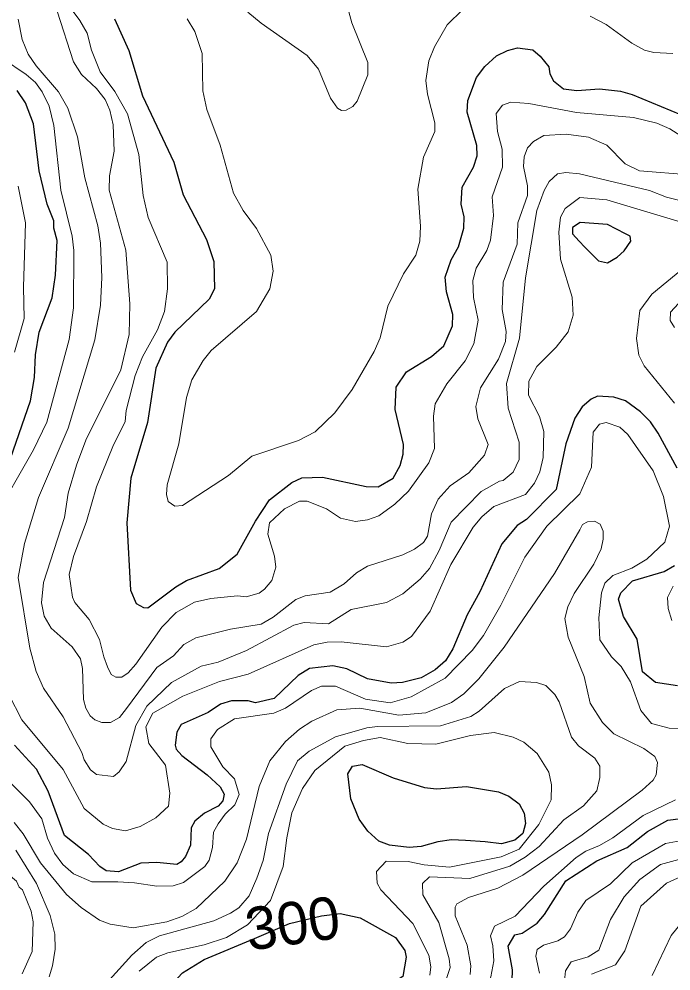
# Model space of a CAD drawing. Extents: x 673.6 to 698.9, y 7012 to 7040.1.
# Drawn here: x 682.325 to 683.554, y 7019.584 to 7021.378 of the extents above; entities that cross this region are included whole.
import ezdxf
from ezdxf.enums import TextEntityAlignment as Align

# ---------------------------------------------------------------- set-up
doc = ezdxf.new("R2010")
doc.units = 0
doc.header["$LTSCALE"] = 0.032
doc.layers.add('1', color=7, linetype='Continuous', lineweight=25)
doc.layers.add('2', color=7, linetype='Continuous', lineweight=13)
doc.layers.add('61', color=7, linetype='Continuous')

msp = doc.modelspace()

# ---------------------------------------------------------------- linework, layer by layer
at = {"layer": '1'}
for points in [[(682.5051, 7021.3782), (682.5322, 7021.3183), (682.5575, 7021.2333), (682.6166, 7021.1083), (682.6346, 7021.0462), (682.6782, 7020.9624), (682.6922, 7020.9209), (682.6932, 7020.8691), (682.6835, 7020.8501), (682.6189, 7020.7875), (682.6051, 7020.7686), (682.5829, 7020.72), (682.5674, 7020.6173), (682.536, 7020.5124), (682.528, 7020.4286), (682.5349, 7020.3014), (682.546, 7020.2763), (682.5597, 7020.2687)], [(682.7363, 7020.3695), (682.7705, 7020.4316), (682.7972, 7020.4719), (682.8393, 7020.5047), (682.8583, 7020.5134), (682.8969, 7020.5142), (682.9792, 7020.4972), (683.0017, 7020.4962), (683.0302, 7020.5129), (683.0432, 7020.5367), (683.0489, 7020.5578), (683.0497, 7020.5758), (683.0341, 7020.6419), (683.0358, 7020.6839), (683.0555, 7020.713), (683.1026, 7020.7421), (683.1256, 7020.7619), (683.1417, 7020.7997), (683.1424, 7020.8211), (683.1307, 7020.8634), (683.1279, 7020.8913), (683.1392, 7020.9238), (683.1534, 7020.9482), (683.1634, 7020.9839), (683.1639, 7021.0051), (683.1583, 7021.029), (683.1599, 7021.0611), (683.1814, 7021.0988), (683.1886, 7021.1202), (683.1879, 7021.1393), (683.1698, 7021.2021), (683.1708, 7021.2242), (683.1869, 7021.2673), (683.2029, 7021.2885), (683.2251, 7021.3082), (683.2454, 7021.3186), (683.2647, 7021.3235), (683.2935, 7021.3196), (683.3072, 7021.3077), (683.3232, 7021.2874), (683.3251, 7021.2743), (683.3325, 7021.2612), (683.3514, 7021.2465), (683.3764, 7021.2431), (683.4188, 7021.2462), (683.4586, 7021.2415), (683.4807, 7021.2355), (683.6263, 7021.175)], [(682.3087, 7020.5499), (682.3464, 7020.6584), (682.3545, 7020.7024), (682.3561, 7020.7447), (682.3627, 7020.7874), (682.3875, 7020.8523), (682.394, 7020.895), (682.3972, 7020.9604), (682.3908, 7020.9838), (682.3906, 7020.9973), (682.3781, 7021.0286), (682.3628, 7021.0915), (682.3521, 7021.1801), (682.3375, 7021.2197), (682.3216, 7021.243)], [(683.5653, 7020.5312), (683.5294, 7020.5975), (683.5148, 7020.6185), (683.4964, 7020.6377), (683.4679, 7020.6585), (683.4458, 7020.6653), (683.415, 7020.667), (683.4032, 7020.6612), (683.3863, 7020.6468), (683.3725, 7020.6255), (683.3553, 7020.5771), (683.3371, 7020.4911), (683.2812, 7020.4349), (683.2635, 7020.4237), (683.2348, 7020.3891), (683.1937, 7020.2984), (683.1696, 7020.255), (683.1426, 7020.1912), (683.1286, 7020.1683)], [(682.5597, 7020.2687), (682.568, 7020.268), (682.6205, 7020.3077), (682.6409, 7020.3196), (682.7025, 7020.3423), (682.7363, 7020.3695)], [(683.5658, 7020.1213), (683.5248, 7020.1276), (683.5002, 7020.1477), (683.4902, 7020.2093), (683.4642, 7020.2517), (683.455, 7020.2845), (683.459, 7020.2964), (683.4812, 7020.3194), (683.5411, 7020.3369), (683.56, 7020.3482)], [(683.1286, 7020.1683), (683.1092, 7020.1512), (683.0831, 7020.1361), (683.0477, 7020.1279), (683.0263, 7020.1264), (682.982, 7020.1347)], [(682.982, 7020.1347), (682.9425, 7020.1535), (682.9166, 7020.1591), (682.8727, 7020.1543), (682.851, 7020.141), (682.8058, 7020.0973), (682.7707, 7020.0894), (682.7569, 7020.0928), (682.7257, 7020.0933), (682.7047, 7020.0868), (682.6816, 7020.0713), (682.6309, 7020.0484), (682.6224, 7020.0338), (682.6192, 7020.0093), (682.621, 7020.002), (682.6316, 7019.99), (682.6799, 7019.9537), (682.7043, 7019.9309), (682.7116, 7019.9175), (682.7094, 7019.9045), (682.7006, 7019.8948), (682.6747, 7019.8812), (682.6562, 7019.8666), (682.6496, 7019.854), (682.648, 7019.8214), (682.6386, 7019.7998), (682.6306, 7019.7895), (682.6227, 7019.785), (682.5846, 7019.7885), (682.5545, 7019.7869), (682.5126, 7019.7706), (682.4892, 7019.7728), (682.4772, 7019.7809), (682.4561, 7019.8036), (682.4107, 7019.8393), (682.3797, 7019.9226), (682.3578, 7019.9644), (682.3168, 7020.0095)], [(683.2543, 7019.5654), (683.2551, 7019.5863), (683.2471, 7019.6308), (683.2597, 7019.6522), (683.2732, 7019.6555), (683.3018, 7019.6742), (683.3156, 7019.6907), (683.3555, 7019.754), (683.4137, 7019.7918), (683.4713, 7019.8169), (683.5096, 7019.8466), (683.5478, 7019.8682), (683.5917, 7019.874)]]:
    msp.add_lwpolyline(points, dxfattribs=at)
for points in [[(683.4678, 7020.973), (683.4341, 7020.9906), (683.3828, 7020.9944), (683.3682, 7020.9852), (683.3682, 7020.973), (683.3805, 7020.9592), (683.3912, 7020.9477), (683.4173, 7020.9224), (683.4341, 7020.9186), (683.4525, 7020.9293), (683.4655, 7020.9408), (683.4778, 7020.9592), (683.477, 7020.9684)], [(683.2038, 7019.8274), (683.1666, 7019.8296), (683.1402, 7019.8312), (683.1145, 7019.8274), (683.0826, 7019.8184), (683.0603, 7019.8166), (683.0234, 7019.8211), (683.0033, 7019.8287), (682.9821, 7019.8473), (682.9661, 7019.8698), (682.9504, 7019.9082), (682.9446, 7019.9558), (682.9538, 7019.97), (682.9715, 7019.9732), (683.0304, 7019.9478), (683.0889, 7019.93), (683.1116, 7019.9275), (683.1681, 7019.9315), (683.2286, 7019.9217), (683.2483, 7019.9136), (683.2677, 7019.8991), (683.2771, 7019.8813), (683.2797, 7019.8618), (683.2745, 7019.843), (683.2595, 7019.8303), (683.2344, 7019.8238)], [(682.7689, 7019.645), (682.8348, 7019.6735), (682.8948, 7019.6881), (682.9305, 7019.6926), (682.9679, 7019.6841), (683.0345, 7019.6474), (683.0518, 7019.6229), (683.0546, 7019.6099), (683.0482, 7019.5736), (683.0237, 7019.5578), (682.9759, 7019.5445), (682.9475, 7019.5267), (682.8657, 7019.4469), (682.8237, 7019.4132), (682.7678, 7019.4058), (682.6934, 7019.4212), (682.6532, 7019.4424), (682.6206, 7019.4716), (682.6079, 7019.4891), (682.5978, 7019.5153), (682.6028, 7019.5443), (682.6071, 7019.5529), (682.6329, 7019.5804), (682.6738, 7019.6055)]]:
    msp.add_lwpolyline(points, close=True, dxfattribs=at)
at = {"layer": '2'}
for points in [[(682.9372, 7021.4266), (682.9523, 7021.3707), (682.9822, 7021.296), (682.9825, 7021.2727), (682.9622, 7021.2227), (682.9541, 7021.2127), (682.9417, 7021.206), (682.933, 7021.2053), (682.9252, 7021.21), (682.9118, 7021.2283), (682.8892, 7021.2832), (682.8681, 7021.3088), (682.7811, 7021.3699), (682.7563, 7021.3909)], [(683.033, 7020.4637), (683.0034, 7020.4417), (682.9815, 7020.4338), (682.959, 7020.4312), (682.9307, 7020.437), (682.9045, 7020.4547), (682.8682, 7020.469), (682.8539, 7020.4691), (682.8251, 7020.4551), (682.7973, 7020.4285), (682.7942, 7020.4073), (682.8065, 7020.3654), (682.8089, 7020.3451), (682.8012, 7020.3197), (682.7879, 7020.3033), (682.7778, 7020.2961), (682.7531, 7020.2892), (682.7367, 7020.2907), (682.6862, 7020.2857), (682.6557, 7020.2792), (682.6214, 7020.2592), (682.5939, 7020.2317), (682.5454, 7020.1619), (682.5307, 7020.1461), (682.5187, 7020.1379), (682.5076, 7020.1379), (682.4988, 7020.1425), (682.4919, 7020.1573), (682.4846, 7020.1757), (682.4764, 7020.2086), (682.4571, 7020.2463), (682.4304, 7020.2781), (682.4257, 7020.2886), (682.4195, 7020.3309), (682.428, 7020.365), (682.4519, 7020.4307), (682.471, 7020.4962), (682.5016, 7020.5723), (682.5253, 7020.6192), (682.5272, 7020.6403), (682.5438, 7020.7063), (682.558, 7020.7412), (682.5861, 7020.7924), (682.5992, 7020.8265), (682.6051, 7020.8693), (682.6043, 7020.9198), (682.5681, 7021.0035), (682.5592, 7021.0455), (682.5508, 7021.1222), (682.5294, 7021.199), (682.5059, 7021.2411), (682.4782, 7021.2783), (682.4617, 7021.3191), (682.4532, 7021.3512), (682.4396, 7021.3752), (682.4137, 7021.4098)], [(682.3967, 7021.3927), (682.4278, 7021.297), (682.443, 7021.2731), (682.471, 7021.2466), (682.4872, 7021.226), (682.4962, 7021.2063), (682.5025, 7021.1782), (682.5041, 7021.1289), (682.4958, 7021.0825), (682.4951, 7021.0554), (682.5262, 7020.9423), (682.5337, 7020.8411), (682.5328, 7020.7833), (682.5171, 7020.7168), (682.4507, 7020.5841), (682.4332, 7020.5373), (682.4179, 7020.4841), (682.4106, 7020.4384), (682.3709, 7020.3158), (682.3677, 7020.2779), (682.3725, 7020.2527), (682.3857, 7020.2299), (682.4255, 7020.195), (682.4408, 7020.1723), (682.4449, 7020.1538), (682.4466, 7020.0956), (682.4508, 7020.0791)], [(683.1613, 7021.3957), (683.1316, 7021.3665), (683.108, 7021.3253), (683.0971, 7021.2989), (683.0917, 7021.2621), (683.0951, 7021.2359), (683.1089, 7021.1822), (683.1089, 7021.1659), (683.0876, 7021.1177), (683.0768, 7021.057), (683.0817, 7020.9874), (683.0802, 7020.9591), (683.0727, 7020.9325), (683.0496, 7020.8976), (683.0198, 7020.8365), (683.0055, 7020.777), (682.9943, 7020.7511), (682.9529, 7020.6796), (682.9205, 7020.6355), (682.8832, 7020.5999), (682.8519, 7020.5838), (682.7638, 7020.5543), (682.7196, 7020.5178), (682.6331, 7020.4609), (682.6184, 7020.4596), (682.6058, 7020.4688), (682.6028, 7020.4818), (682.6043, 7020.4999), (682.6265, 7020.5775), (682.6405, 7020.6645), (682.6507, 7020.698), (682.6722, 7020.7346), (682.687, 7020.753), (682.7728, 7020.8268), (682.7979, 7020.8694), (682.804, 7020.9028), (682.7998, 7020.933), (682.7724, 7020.9828), (682.7473, 7021.0168), (682.729, 7021.0499), (682.7044, 7021.1403), (682.6787, 7021.2071), (682.6717, 7021.2427), (682.6699, 7021.3128), (682.6564, 7021.3542), (682.6421, 7021.3778)], [(683.578, 7021.0341), (683.5452, 7021.0423), (683.5129, 7021.0549), (683.3814, 7021.0862), (683.3555, 7021.0886), (683.3398, 7021.0862), (683.3242, 7021.0718), (683.3145, 7021.0544), (683.3006, 7021.0168), (683.2795, 7020.8902), (683.2683, 7020.7764), (683.2437, 7020.6908), (683.2469, 7020.6443), (683.2677, 7020.5805), (683.2675, 7020.5479), (683.2565, 7020.5237), (683.2377, 7020.508), (683.2308, 7020.5072), (683.1958, 7020.4876), (683.1396, 7020.4297), (683.117, 7020.3766), (683.0984, 7020.3427), (683.0811, 7020.3222), (683.0481, 7020.2947), (683.0176, 7020.2786), (682.9508, 7020.265), (682.9081, 7020.238), (682.8625, 7020.2404), (682.8431, 7020.2357), (682.7539, 7020.1879), (682.7004, 7020.166), (682.6681, 7020.1582), (682.6124, 7020.1277), (682.5662, 7020.0833), (682.5453, 7020.0466), (682.5269, 7019.9789), (682.5139, 7019.9595), (682.5032, 7019.9506), (682.4712, 7019.9544), (682.4599, 7019.9628), (682.4476, 7019.9819), (682.4431, 7019.9959), (682.4081, 7020.0627), (682.3711, 7020.1169), (682.3572, 7020.1482), (682.3456, 7020.1925), (682.3234, 7020.3256), (682.3356, 7020.3898), (682.3617, 7020.4765), (682.4177, 7020.6067), (682.4679, 7020.773), (682.4786, 7020.8384), (682.4811, 7020.8906), (682.4788, 7020.9552), (682.4736, 7020.9883), (682.4491, 7021.0784), (682.435, 7021.1559), (682.4173, 7021.2095), (682.3994, 7021.2408), (682.3576, 7021.2894), (682.3425, 7021.3118), (682.3308, 7021.339), (682.3234, 7021.3775)], [(683.5573, 7021.3129), (683.5211, 7021.3146), (683.504, 7021.3191), (683.4796, 7021.332), (683.4315, 7021.3673), (683.4013, 7021.3832)], [(682.294, 7021.3036), (682.3388, 7021.2733), (682.3559, 7021.2581), (682.3689, 7021.2405), (682.3816, 7021.2135), (682.3907, 7021.1773), (682.4039, 7021.0554), (682.4252, 7020.9686), (682.4285, 7020.9413), (682.4276, 7020.8338), (682.4193, 7020.7739), (682.3774, 7020.6182), (682.3523, 7020.5662), (682.2756, 7020.4328)], [(683.584, 7021.1498), (683.5514, 7021.1706), (683.5271, 7021.1812), (683.4833, 7021.1922), (683.3755, 7021.2019), (683.2856, 7021.2183), (683.2521, 7021.2209), (683.236, 7021.2157), (683.224, 7021.1999), (683.2265, 7021.1655), (683.2355, 7021.1322), (683.2363, 7021.0988), (683.2166, 7021.0429), (683.219, 7021.0077), (683.2138, 7020.9608), (683.2064, 7020.9417), (683.1863, 7020.9081), (683.1805, 7020.8852), (683.1813, 7020.8532), (683.1902, 7020.8105), (683.1823, 7020.766), (683.1656, 7020.7336), (683.1311, 7020.6904), (683.109, 7020.6528)], [(682.5143, 7020.0619), (682.5277, 7020.0784), (682.5847, 7020.1558), (682.6163, 7020.1777), (682.6359, 7020.1989), (682.6583, 7020.2115), (682.7238, 7020.2284), (682.7811, 7020.2376), (682.8039, 7020.2505), (682.8468, 7020.284), (682.8641, 7020.2906), (682.9117, 7020.2981), (682.9377, 7020.3133), (682.961, 7020.3342), (682.982, 7020.3471), (683.0481, 7020.3681), (683.0701, 7020.3789), (683.0873, 7020.3917), (683.095, 7020.4031), (683.1021, 7020.4452), (683.1149, 7020.4729), (683.1374, 7020.4983), (683.173, 7020.5225), (683.2024, 7020.5558), (683.209, 7020.5758), (683.1898, 7020.6242), (683.1862, 7020.6476), (683.1946, 7020.6826), (683.2284, 7020.7367), (683.2417, 7020.7702), (683.2428, 7020.7891), (683.2355, 7020.8302), (683.2372, 7020.882), (683.2641, 7020.9535), (683.2651, 7020.9937), (683.2832, 7021.0449), (683.2832, 7021.0632), (683.2758, 7021.0998), (683.2768, 7021.1183), (683.2832, 7021.1353), (683.2949, 7021.1468), (683.3139, 7021.1584), (683.3562, 7021.161), (683.3982, 7021.1551), (683.4327, 7021.1398), (683.4674, 7021.1049), (683.4942, 7021.0916), (683.5891, 7021.0843)], [(682.3237, 7021.0627), (682.3371, 7020.9935), (682.3332, 7020.8727), (682.3348, 7020.8134), (682.3168, 7020.75)], [(682.3057, 7020.1047), (682.3304, 7020.0571), (682.4083, 7019.9638), (682.4478, 7019.8899), (682.4834, 7019.8605), (682.5011, 7019.8526), (682.5259, 7019.8479), (682.5531, 7019.8566), (682.583, 7019.8724), (682.6068, 7019.8949), (682.6092, 7019.9191), (682.601, 7019.9719), (682.5698, 7020.0126), (682.5641, 7020.0439), (682.5769, 7020.0697), (682.6335, 7020.1017), (682.7026, 7020.1294), (682.7571, 7020.1433), (682.8804, 7020.1986), (682.9058, 7020.2036), (682.9322, 7020.2044), (683.0174, 7020.1949), (683.0486, 7020.2039), (683.0645, 7020.2143), (683.1001, 7020.2623), (683.1389, 7020.3497), (683.181, 7020.4202), (683.1971, 7020.4396), (683.2199, 7020.4591), (683.2796, 7020.4821), (683.2963, 7020.5032), (683.3066, 7020.5243), (683.3128, 7020.5515), (683.3143, 7020.6004), (683.306, 7020.6287), (683.2849, 7020.6692), (683.2855, 7020.6955), (683.3011, 7020.7231), (683.337, 7020.7596), (683.36, 7020.7883), (683.3694, 7020.82), (683.3677, 7020.8539), (683.3454, 7020.9254), (683.3424, 7020.9759), (683.3455, 7021.0042), (683.3544, 7021.0208), (683.3821, 7021.0417), (683.4327, 7021.0368), (683.5836, 7020.9917)], [(683.5918, 7020.92), (683.5179, 7020.8591), (683.4952, 7020.8287), (683.4885, 7020.7755), (683.4933, 7020.7441), (683.5032, 7020.7244), (683.5604, 7020.6542)], [(683.5605, 7020.7963), (683.5519, 7020.8098), (683.5529, 7020.8251), (683.6056, 7020.8823)], [(683.109, 7020.6528), (683.1064, 7020.6292), (683.1081, 7020.5684), (683.0976, 7020.5417), (683.0591, 7020.4881), (683.033, 7020.4637)], [(682.2915, 7019.956), (682.3445, 7019.903), (682.3681, 7019.8708), (682.3788, 7019.834), (682.3917, 7019.8059), (682.4076, 7019.7848), (682.4279, 7019.767), (682.4624, 7019.7518), (682.5113, 7019.7522), (682.5426, 7019.7499), (682.585, 7019.744), (682.6155, 7019.7442), (682.6353, 7019.7506), (682.6753, 7019.7807), (682.6831, 7019.7928), (682.6898, 7019.8165), (682.6915, 7019.8453), (682.7004, 7019.8616), (682.7137, 7019.8797), (682.7319, 7019.8973), (682.7399, 7019.9167), (682.7308, 7019.9464), (682.7092, 7019.9688), (682.6866, 7020.0067), (682.6867, 7020.0216), (682.6988, 7020.039), (682.7314, 7020.0589), (682.8053, 7020.0697), (682.8273, 7020.0793), (682.8763, 7020.1123), (682.8951, 7020.1207), (682.9215, 7020.1205), (682.978, 7020.0963), (683.0246, 7020.0894), (683.0642, 7020.1007), (683.1284, 7020.1358), (683.1793, 7020.1877), (683.2002, 7020.2164), (683.2329, 7020.2735), (683.2781, 7020.3635), (683.3196, 7020.4224), (683.3821, 7020.4828), (683.4039, 7020.5331), (683.4071, 7020.599), (683.4188, 7020.6144), (683.4316, 7020.6176), (683.4573, 7020.6086), (683.4724, 7020.5952), (683.5198, 7020.5265), (683.5398, 7020.4782), (683.551, 7020.4222), (683.5418, 7020.3923), (683.5083, 7020.3597), (683.4798, 7020.343), (683.4441, 7020.3294), (683.4288, 7020.3147), (683.4229, 7020.2964), (683.418, 7020.2494), (683.4196, 7020.208), (683.4414, 7020.176), (683.4597, 7020.1575), (683.4777, 7020.1286), (683.4967, 7020.0749), (683.5169, 7020.0506), (683.5503, 7020.0417), (683.5783, 7020.041)], [(682.3159, 7019.8641), (682.3327, 7019.8422), (682.3658, 7019.788), (682.4143, 7019.728), (682.4422, 7019.7039), (682.4764, 7019.68), (682.497, 7019.6724), (682.5402, 7019.6654), (682.6037, 7019.6767), (682.632, 7019.6865), (682.6586, 7019.7015), (682.7129, 7019.7533), (682.7362, 7019.7876), (682.7538, 7019.8326), (682.7779, 7019.9315), (682.7978, 7019.9799), (682.8273, 7020.0164), (682.8536, 7020.0396), (682.8766, 7020.055), (682.924, 7020.076), (682.9676, 7020.0794), (683.041, 7020.0662), (683.0919, 7020.0703), (683.1398, 7020.09), (683.1633, 7020.1061), (683.1915, 7020.1348), (683.2391, 7020.1939), (683.3344, 7020.3327), (683.3819, 7020.415), (683.387, 7020.4253), (683.3966, 7020.4302), (683.4093, 7020.4313), (683.4205, 7020.4261), (683.4261, 7020.4128), (683.4257, 7020.3978), (683.4222, 7020.3797), (683.4082, 7020.3506), (683.3712, 7020.2951), (683.3593, 7020.27)], [(683.5578, 7020.3093), (683.547, 7020.2879), (683.5485, 7020.2668), (683.5556, 7020.2445)], [(683.3593, 7020.27), (683.3538, 7020.2479), (683.3601, 7020.2133), (683.3898, 7020.1389), (683.4012, 7020.0885)], [(683.1234, 7019.548), (683.1375, 7019.5906), (683.1354, 7019.6072), (683.116, 7019.6757), (683.0858, 7019.7273), (683.0853, 7019.7492), (683.0986, 7019.7614), (683.1743, 7019.7581), (683.2498, 7019.7817), (683.2791, 7019.7983), (683.305, 7019.8187), (683.3516, 7019.8686), (683.3887, 7019.895), (683.4142, 7019.9237), (683.4196, 7019.9487), (683.4194, 7019.9701), (683.4104, 7019.9849), (683.3795, 7020.0085), (683.3665, 7020.0246), (683.3431, 7020.0911), (683.3349, 7020.1049), (683.3179, 7020.122), (683.3002, 7020.1278), (683.2681, 7020.1294), (683.2398, 7020.116), (683.1925, 7020.0733), (683.1768, 7020.0637), (683.1191, 7020.0458), (683.0005, 7020.0449), (682.9808, 7020.0424), (682.9216, 7020.0252), (682.8718, 7019.998), (682.8501, 7019.98), (682.8285, 7019.9362), (682.7951, 7019.8428), (682.7852, 7019.7925), (682.7735, 7019.7589), (682.7585, 7019.7254), (682.7392, 7019.703), (682.7237, 7019.6929), (682.6923, 7019.6788), (682.5895, 7019.6505), (682.5644, 7019.6375), (682.5375, 7019.6141), (682.4834, 7019.554)], [(682.4508, 7020.0791), (682.4592, 7020.0649), (682.4677, 7020.0574), (682.4808, 7020.0523), (682.4974, 7020.0524), (682.5143, 7020.0619)], [(683.4012, 7020.0885), (683.4248, 7020.0522), (683.446, 7020.0307), (683.5028, 7020.0032), (683.523, 7019.9879), (683.528, 7019.9771), (683.526, 7019.9539), (683.5201, 7019.9435), (683.4995, 7019.925), (683.3861, 7019.8403), (683.2743, 7019.7645), (683.2276, 7019.7402), (683.1719, 7019.7224), (683.1502, 7019.7106), (683.1468, 7019.7043), (683.1469, 7019.6878), (683.1695, 7019.6326), (683.1764, 7019.594), (683.1754, 7019.5777)], [(682.5512, 7019.5834), (682.5839, 7019.6102), (682.6057, 7019.6183), (682.6742, 7019.6334), (682.7158, 7019.6471), (682.7559, 7019.6708), (682.7987, 7019.7166), (682.823, 7019.7807), (682.8296, 7019.835), (682.8393, 7019.8822), (682.859, 7019.9279), (682.8827, 7019.9617), (682.939, 7020.0075), (682.9742, 7020.0186), (683.0059, 7020.0237), (683.0576, 7020.0129), (683.1105, 7020.0113), (683.176, 7020.0276), (683.2207, 7020.0334), (683.2562, 7020.0247), (683.2765, 7020.0153), (683.3012, 7019.9939), (683.3233, 7019.9589), (683.3283, 7019.9348), (683.328, 7019.9063), (683.3049, 7019.8603), (683.2674, 7019.8135), (683.2335, 7019.7992), (683.1364, 7019.7799), (683.0887, 7019.7841), (683.0583, 7019.7902), (683.0172, 7019.7909), (682.999, 7019.7713), (683, 7019.7494), (683.0068, 7019.7372), (683.067, 7019.6735), (683.0976, 7019.6136), (683.1014, 7019.5921), (683.099, 7019.5763)], [(682.0876, 7020.0193), (682.1178, 7019.9677), (682.1362, 7019.9111), (682.1649, 7019.8387), (682.1974, 7019.8145), (682.2852, 7019.7822), (682.3205, 7019.7534), (682.3251, 7019.7418), (682.3313, 7019.7367), (682.3481, 7019.697), (682.352, 7019.6765), (682.3496, 7019.6209), (682.3311, 7019.5789)], [(683.5622, 7019.9068), (683.5014, 7019.8772), (683.4443, 7019.8352), (683.4192, 7019.8205), (683.3935, 7019.8101), (683.3753, 7019.798), (683.3143, 7019.7441), (683.2598, 7019.6871), (683.2208, 7019.6685), (683.2133, 7019.6503), (683.2181, 7019.6312)], [(683.8814, 7019.8888), (683.8862, 7019.8695), (683.9168, 7019.8113), (683.928, 7019.7741), (683.9145, 7019.7536), (683.8985, 7019.744), (683.8667, 7019.7381), (683.8338, 7019.7367), (683.7686, 7019.7262), (683.7391, 7019.7244), (683.7049, 7019.7284), (683.6912, 7019.7332), (683.6299, 7019.7672), (683.6106, 7019.7704), (683.5864, 7019.7682), (683.5455, 7019.7495), (683.4966, 7019.7061), (683.4668, 7019.622), (683.4493, 7019.5959), (683.4038, 7019.5778)], [(683.5777, 7019.8305), (683.5432, 7019.8241), (683.4806, 7019.7877), (683.44, 7019.7484), (683.3933, 7019.717), (683.3784, 7019.6948), (683.3645, 7019.6637), (683.3532, 7019.6484), (683.3402, 7019.6407), (683.3135, 7019.6327), (683.3013, 7019.6245), (683.2988, 7019.6121), (683.3061, 7019.5798)], [(682.3817, 7019.5732), (682.3884, 7019.5937), (682.393, 7019.6252), (682.3923, 7019.6535), (682.384, 7019.6886), (682.3578, 7019.7491), (682.319, 7019.8119)], [(683.352, 7019.5528), (683.3546, 7019.5844), (683.3655, 7019.6015), (683.3976, 7019.6107), (683.4177, 7019.6234), (683.4399, 7019.6812), (683.4655, 7019.7239), (683.4949, 7019.7563), (683.5341, 7019.7845), (683.5757, 7019.7959)], [(683.5181, 7019.5757), (683.554, 7019.6512), (683.5812, 7019.6839), (683.5945, 7019.6932), (683.6159, 7019.7013), (683.6435, 7019.694), (683.6723, 7019.6737), (683.6935, 7019.6634), (683.719, 7019.6604), (683.7622, 7019.6711), (683.8038, 7019.6703), (683.8377, 7019.6583), (683.8586, 7019.6445), (683.878, 7019.6234)], [(683.2181, 7019.6312), (683.2198, 7019.6032), (683.2141, 7019.5732), (683.177, 7019.4973), (683.1274, 7019.4247), (683.1136, 7019.4102)]]:
    msp.add_lwpolyline(points, dxfattribs=at)

# ---------------------------------------------------------------- texts
at = {"layer": '61'}
msp.add_text('300', height=0.08, rotation=8.056, dxfattribs=at).set_placement((682.846, 7019.6346), align=Align.CENTER)

doc.saveas('drawing.dxf')
